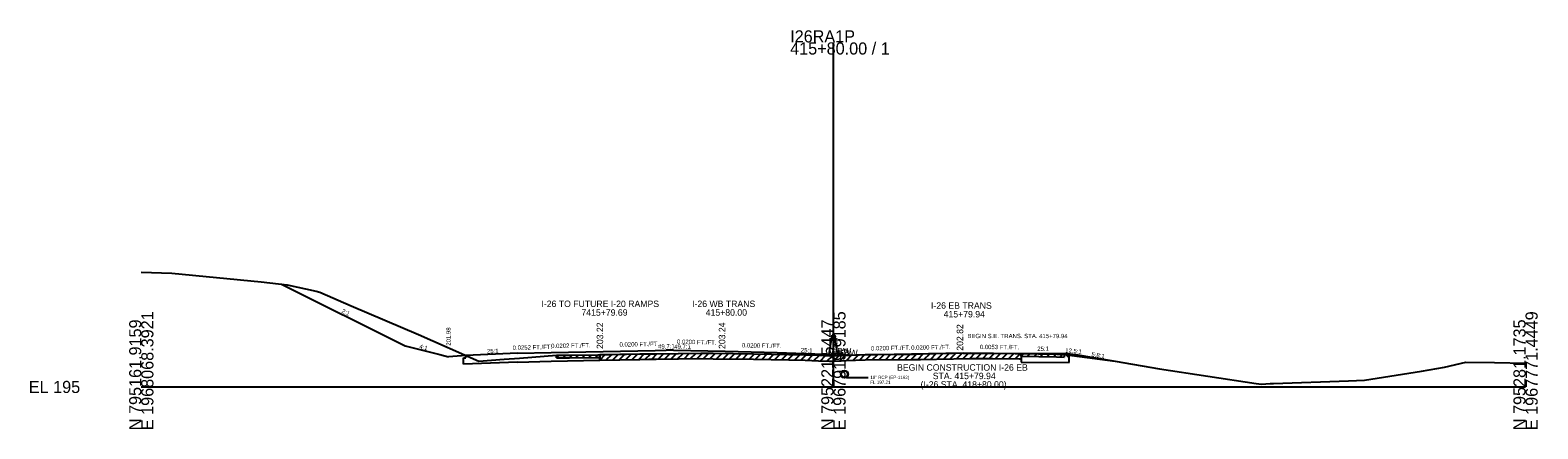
# Model space of a CAD drawing. Extents: x -44 to 4323, y -10 to 9601.
# Drawn here: x -25.7 to 322.8, y 9490.3 to 9582.5 of the extents above; entities that cross this region are included whole.
import ezdxf

# ---------------------------------------------------------------- set-up
doc = ezdxf.new("R2010")
doc.units = 0
for name, color, linetype in [('1', 7, 'Continuous'), ('DateStamp', 7, 'Continuous'), ('NotForConst', 7, 'Continuous'), ('QCQA', 7, 'Continuous'), ('RD_SHT_Bndy', 7, 'Continuous'), ('RD_SHT_Iplotshp', 7, 'Continuous'), ('RD_SHT_TX', 7, 'Continuous'), ('RD_TX_Misc1', 7, 'Continuous'), ('RD_XS_ExGround', 7, 'Continuous'), ('RD_XS_MatchLine', 7, 'Continuous'), ('RD_XS_MedBWall', 7, 'Continuous'), ('RD_XS_Misc_Line', 7, 'Continuous'), ('RD_XS_Pave', 7, 'Continuous'), ('RD_XS_PaveShd', 7, 'Continuous'), ('RD_XS_Pipe', 7, 'Continuous'), ('RD_XS_TX_Elev_PR', 7, 'Continuous'), ('RD_XS_TX_Profile', 7, 'Continuous'), ('RD_XS_TX_ShdSlope', 7, 'Continuous'), ('RD_XS_TX_Slope', 7, 'Continuous'), ('seal', 7, 'Continuous'), ('TR SN EXTRUDED PANEL SIGNS - GROUND MOUNTED', 7, 'Continuous')]:
    doc.layers.add(name, color=color, linetype=linetype)

msp = doc.modelspace()

# ---------------------------------------------------------------- linework, layer by layer
at = {"layer": 'DateStamp'}
msp.add_lwpolyline([(0, 9526.56), (7.08, 9526.33), (27.72, 9524.3), (33.69, 9523.63), (40.4, 9522.11), (41.25, 9521.9), (48.53, 9518.76), (64.07, 9512.11), (78.01, 9505.96), (83.92, 9506.41), (87.46, 9506.68), (95.99, 9507.33), (99.16, 9507.38), (105.5, 9507.46), (115.46, 9507.64), (117.36, 9507.67), (118.85, 9507.69), (129.37, 9507.82), (131.97, 9507.79), (141.49, 9507.69), (149.91, 9507.5), (153.45, 9507.42), (156.37, 9507.31), (159.09, 9507.2), (160, 9507.24), (161.79, 9507.32), (163.33, 9507.37), (167.35, 9507.49), (178.64, 9507.61), (180.16, 9507.63), (183.47, 9507.7), (191.8, 9507.86), (197.04, 9507.81), (202.99, 9507.75), (211.72, 9507.56), (213.37, 9507.52), (225.16, 9505.96), (235.35, 9504.22), (257.71, 9500.8), (258.92, 9500.66), (260.96, 9500.76), (261.72, 9500.78), (279.1, 9501.4), (282.77, 9501.55), (295.95, 9503.68), (301.23, 9504.61), (306.19, 9505.7), (312.82, 9505.62), (320, 9505.47)], dxfattribs=at)
at = {"layer": 'NotForConst'}
for p, q in [((95.99, 9506.71), (96.63, 9507.34)), ((97.49, 9506.73), (98.13, 9507.36)), ((98.99, 9506.75), (99.63, 9507.38)), ((100.49, 9506.77), (101.13, 9507.4)), ((101.99, 9506.79), (102.63, 9507.42)), ((103.49, 9506.81), (104.13, 9507.44)), ((104.99, 9506.83), (105.63, 9507.46)), ((105.99, 9506.22), (107.27, 9507.49)), ((107.49, 9506.24), (108.77, 9507.52)), ((108.99, 9506.27), (110.27, 9507.54)), ((110.49, 9506.3), (111.77, 9507.57)), ((111.99, 9506.32), (113.27, 9507.6)), ((113.49, 9506.35), (114.77, 9507.62)), ((114.99, 9506.38), (116.27, 9507.65)), ((116.49, 9506.4), (117.77, 9507.68)), ((117.99, 9506.43), (119.26, 9507.7)), ((119.49, 9506.45), (120.76, 9507.71)), ((120.99, 9506.47), (122.26, 9507.73)), ((122.49, 9506.48), (123.76, 9507.75)), ((123.99, 9506.5), (125.26, 9507.77)), ((125.49, 9506.52), (126.76, 9507.79)), ((126.99, 9506.54), (128.26, 9507.8)), ((128.49, 9506.56), (129.75, 9507.81)), ((129.99, 9506.56), (131.23, 9507.79)), ((131.49, 9506.54), (132.73, 9507.78)), ((132.99, 9506.52), (134.23, 9507.76)), ((134.49, 9506.51), (135.73, 9507.75)), ((135.99, 9506.49), (137.23, 9507.73)), ((137.49, 9506.48), (138.73, 9507.72)), ((138.99, 9506.46), (140.23, 9507.7)), ((140.49, 9506.45), (141.73, 9507.68)), ((141.99, 9506.43), (143.22, 9507.65)), ((143.49, 9506.39), (144.72, 9507.62)), ((144.99, 9506.36), (146.22, 9507.58)), ((146.49, 9506.33), (147.72, 9507.55)), ((147.99, 9506.29), (149.22, 9507.51)), ((149.49, 9506.26), (150.72, 9507.48)), ((150.99, 9506.22), (152.22, 9507.45)), ((152.49, 9506.19), (153.71, 9507.41)), ((153.99, 9506.15), (155.2, 9507.35)), ((155.49, 9506.09), (156.7, 9507.3)), ((156.99, 9506.04), (158.19, 9507.24)), ((158.49, 9505.97), (159.75, 9507.23)), ((159.99, 9505.99), (161.3, 9507.3)), ((161.49, 9506.06), (162.79, 9507.35)), ((162.99, 9506.11), (164.28, 9507.4)), ((164.49, 9506.15), (165.78, 9507.44)), ((165.99, 9506.2), (167.28, 9507.49)), ((167.49, 9506.24), (168.76, 9507.51)), ((168.99, 9506.26), (170.26, 9507.52)), ((170.5, 9506.27), (171.76, 9507.54)), ((172, 9506.29), (173.26, 9507.55)), ((173.5, 9506.31), (174.76, 9507.57)), ((175, 9506.32), (176.26, 9507.59)), ((176.5, 9506.34), (177.76, 9507.6)), ((178, 9506.36), (179.26, 9507.62)), ((179.5, 9506.37), (180.76, 9507.64)), ((181, 9506.39), (182.27, 9507.67)), ((182.5, 9506.42), (183.77, 9507.7)), ((184, 9506.46), (185.27, 9507.73)), ((185.5, 9506.49), (186.77, 9507.76)), ((187, 9506.51), (188.27, 9507.79)), ((188.5, 9506.54), (189.77, 9507.82)), ((190, 9506.57), (191.27, 9507.85)), ((191.5, 9506.6), (192.74, 9507.85)), ((193, 9506.6), (194.23, 9507.84)), ((194.5, 9506.58), (195.73, 9507.82)), ((196, 9506.57), (197.23, 9507.81)), ((197.5, 9506.56), (198.73, 9507.79)), ((199, 9506.54), (200.23, 9507.78)), ((200.5, 9506.53), (201.73, 9507.76)), ((202, 9506.51), (203.23, 9507.74)), ((203.37, 9507.12), (203.98, 9507.73)), ((204.87, 9507.08), (205.48, 9507.7)), ((206.37, 9507.05), (206.98, 9507.66)), ((207.87, 9507.02), (208.48, 9507.63)), ((209.37, 9506.99), (209.98, 9507.6)), ((210.87, 9506.95), (211.48, 9507.57)), ((212.37, 9506.92), (212.98, 9507.53))]:
    msp.add_line(p, q, dxfattribs=at)
at = {"layer": 'QCQA'}
for p, q in [((105.99, 9507.47), (115.28, 9507.63)), ((105.99, 9507.47), (105.99, 9506.16)), ((115.28, 9507.63), (117.36, 9507.67)), ((117.36, 9507.67), (118.99, 9507.69)), ((118.99, 9507.69), (129.37, 9507.82)), ((129.37, 9507.82), (132.18, 9507.78)), ((132.18, 9507.78), (141.49, 9507.69)), ((141.49, 9507.69), (149.72, 9507.5)), ((149.72, 9507.5), (153.45, 9507.42)), ((153.45, 9507.42), (156.52, 9507.31)), ((156.52, 9507.31), (159.09, 9507.2)), ((159.09, 9507.2), (160, 9507.24)), ((203.37, 9507.74), (203.37, 9505.7))]:
    msp.add_line(p, q, dxfattribs=at)
msp.add_lwpolyline([(202, 9507.76), (202.99, 9507.75), (203.37, 9507.74)], dxfattribs=at)
at = {"layer": 'RD_SHT_Bndy'}
for p, q in [((160, 9500), (160, 9579.67)), ((0, 9500), (160, 9500)), ((160, 9500), (320, 9500))]:
    msp.add_line(p, q, dxfattribs=at)
at = {"layer": 'RD_SHT_Iplotshp'}
for p, q in [((95.99, 9506.71), (95.99, 9507.33)), ((95.99, 9506.71), (98.97, 9506.75)), ((98.97, 9506.75), (105.5, 9506.83)), ((105.5, 9506.83), (105.99, 9506.84)), ((105.99, 9506.22), (105.99, 9507.47)), ((105.99, 9507.47), (105.99, 9506.84)), ((105.99, 9506.22), (115.28, 9506.38)), ((115.28, 9506.38), (117.36, 9506.42)), ((117.36, 9506.42), (118.99, 9506.44)), ((118.99, 9506.44), (129.37, 9506.57)), ((129.37, 9506.57), (132.18, 9506.53)), ((132.18, 9506.53), (141.49, 9506.44)), ((141.49, 9506.44), (149.72, 9506.25)), ((149.72, 9506.25), (153.45, 9506.17)), ((153.45, 9506.17), (156.52, 9506.06)), ((156.52, 9506.06), (159.09, 9505.95)), ((159.09, 9505.95), (160, 9505.99)), ((160, 9505.99), (161.79, 9506.07)), ((161.79, 9506.07), (162.96, 9506.11)), ((162.96, 9506.11), (167.35, 9506.24)), ((167.35, 9506.24), (178.49, 9506.36)), ((178.49, 9506.36), (180.16, 9506.38)), ((180.16, 9506.38), (183.79, 9506.45)), ((183.79, 9506.45), (191.8, 9506.61)), ((191.8, 9506.61), (196.84, 9506.56)), ((196.84, 9506.56), (202.99, 9506.5)), ((202.99, 9506.5), (203.37, 9506.49)), ((203.37, 9507.74), (203.37, 9506.49)), ((203.37, 9507.12), (203.37, 9507.74)), ((203.37, 9507.12), (211.53, 9506.94)), ((211.53, 9506.94), (213.37, 9506.9)), ((213.37, 9507.52), (213.37, 9506.9))]:
    msp.add_line(p, q, dxfattribs=at)
at = {"layer": 'RD_TX_Misc1'}
for p in [(69, 9507.48), (73, 9507.14)]:
    msp.add_line(p, (71, 9506.98), dxfattribs=at)
at = {"layer": 'RD_XS_Misc_Line'}
for p, q in [((74.5, 9506.72), (75, 9506.74)), ((74.5, 9505.24), (74.5, 9506.72)), ((87, 9505.74), (74.5, 9505.24)), ((75, 9506.74), (75, 9507.3)), ((87, 9505.74), (94.77, 9505.94)), ((94.77, 9505.94), (105.99, 9506.16)), ((203.37, 9505.7), (214.5, 9505.64)), ((214, 9507.12), (214, 9507.7)), ((214, 9507.12), (214.5, 9507.12)), ((214.5, 9505.64), (214.5, 9507.12))]:
    msp.add_line(p, q, dxfattribs=at)
at = {"layer": 'RD_XS_Pave'}
for p, q in [((32.42, 9523.77), (61, 9509.48)), ((61, 9509.48), (69, 9507.48)), ((216, 9507.54), (225.16, 9505.96))]:
    msp.add_line(p, q, dxfattribs=at)
at = {"layer": 'RD_XS_PaveShd'}
for p, q in [((75, 9507.3), (73, 9507.14)), ((214, 9507.7), (216, 9507.54))]:
    msp.add_line(p, q, dxfattribs=at)
at = {"layer": 'RD_XS_Pipe'}
msp.add_line((163.04, 9502.21), (168.04, 9502.21), dxfattribs=at)
for radius in [0.85, 0.75]:
    msp.add_circle((162.54, 9502.96), radius, dxfattribs=at)
at = {"layer": 'RD_XS_TX_Elev_PR'}
for p, q in [((118.78, 9508.46), (121.33, 9508.51)), ((123, 9508.48), (121.33, 9508.51)), ((147, 9508), (160, 9507.48)), ((87, 9507.78), (75, 9507.3)), ((160, 9507.48), (160, 9507.1)), ((160, 9507.46), (160, 9507.24)), ((166, 9507.34), (160, 9507.1)), ((202, 9507.76), (214, 9507.7))]:
    msp.add_line(p, q, dxfattribs=at)
at = {"layer": 'RD_XS_TX_ShdSlope'}
for p, q in [((159, 9507.5), (159.67, 9511.98)), ((160.33, 9511.98), (159.67, 9511.98)), ((161.05, 9507.14), (160.33, 9511.98))]:
    msp.add_line(p, q, dxfattribs=at)
at = {"layer": 'RD_XS_TX_Slope'}
for p, q in [((87, 9507.78), (94.77, 9507.98)), ((94.77, 9507.98), (106.77, 9508.22)), ((106.77, 9508.22), (118.78, 9508.46)), ((123, 9508.48), (135, 9508.24)), ((135, 9508.24), (147, 9508)), ((190, 9507.82), (166, 9507.34)), ((190, 9507.82), (202, 9507.76))]:
    msp.add_line(p, q, dxfattribs=at)

# ---------------------------------------------------------------- texts
at = {"layer": '1'}
for s, p in [('I-26 TO FUTURE I-20 RAMPS', (92.5, 9518.47)), ('I-26 WB TRANS', (127.33, 9518.47)), ('I-26 EB TRANS', (182.56, 9518.07)), ('7415+79.69', (101.75, 9516.47)), ('415+80.00', (130.48, 9516.47)), ('415+79.94', (185.48, 9516.07))]:
    msp.add_text(s, height=1.5, dxfattribs=at).set_placement(p)
at = {"layer": 'RD_SHT_Bndy'}
for s, p in [('I26RA1P', (150, 9579.67)), ('415+80.00 / 1', (150, 9576.87)), ('EL 195', (-26, 9498.6))]:
    msp.add_text(s, height=2.8, dxfattribs=at).set_placement(p)
for s, p in [('N 795161.9159', (0, 9490)), ('E 1968068.3921', (2.8, 9490)), ('N 795221.5447', (160, 9490)), ('E 1967919.9185', (162.8, 9490)), ('N 795281.1735', (320, 9490)), ('E 1967771.4449', (322.8, 9490))]:
    msp.add_text(s, height=2.8, rotation=90, dxfattribs=at).set_placement(p)
at = {"layer": 'RD_SHT_TX'}
msp.add_text('202.24', height=1, rotation=90, dxfattribs=at).set_placement((161, 9507.24))
at = {"layer": 'RD_XS_ExGround'}
for s, rotation, p in [('25:1', 2.29, (79.93, 9507.75)), ('49.7:1', 1.1535, (119.48, 9508.85)), ('49.7:1', 1.1535, (123.2, 9508.8)), ('25:1', 357.7094, (152.46, 9508.02)), ('25:1', 2.2903, (160.93, 9507.39)), ('25:1', 0.6258, (207.13, 9508.33))]:
    msp.add_text(s, height=1, rotation=rotation, dxfattribs=at).set_placement(p)
at = {"layer": 'RD_XS_MatchLine'}
for s, height, p in [('BEGIN S.E. TRANS. STA. 415+79.94', 1, (190.98, 9511.28)), ('BEGIN CONSTRUCTION I-26 EB', 1.5, (174.72, 9503.76)), ('(I-26 STA. 418+80.00)', 1.5, (180.13, 9499.83)), ('STA. 415+79.94', 1.5, (182.96, 9501.8))]:
    msp.add_text(s, height=height, dxfattribs=at).set_placement(p)
at = {"layer": 'RD_XS_MedBWall'}
msp.add_text('12.5:1', height=1, rotation=355.4267, dxfattribs=at).set_placement((213.55, 9507.98))
at = {"layer": 'RD_XS_Pipe'}
for s, p in [('18" RCP (EP-1162)', (168.53, 9501.84)), ('FL 197.21', (168.53, 9500.71))]:
    msp.add_text(s, height=0.75, dxfattribs=at).set_placement(p)
at = {"layer": 'RD_XS_TX_Profile'}
for s, p in [('WBW', (159, 9507.48)), ('EBW', (161.05, 9507.14))]:
    msp.add_text(s, height=1.5, dxfattribs=at).set_placement(p)
at = {"layer": 'seal'}
for s, p in [(' 203.22', (106.77, 9508.22)), (' 203.24', (135, 9508.22)), (' 202.82', (190, 9507.82))]:
    msp.add_text(s, height=1.5, rotation=90, dxfattribs=at).set_placement(p)
at = {"layer": 'TR SN EXTRUDED PANEL SIGNS - GROUND MOUNTED'}
for s, rotation, p in [('2:1', 333.4349, (46.2, 9517.24)), ('201.98', 90, (71.5, 9509.54)), ('4:1', 345.9638, (64.2, 9508.92)), ('0.0252 FT./FT.', 1.4427, (85.86, 9508.56)), ('0.0202 FT./FT.', 1.1562, (94.75, 9508.98)), ('0.0200 FT./FT.', 1.1535, (110.56, 9509.3)), ('0.0200 FT./FT.', 358.8542, (123.84, 9509.98)), ('0.0200 FT./FT.', 358.8542, (138.83, 9509.15)), ('0.0200 FT./FT.', 1.1503, (168.7, 9508.42)), ('0.0200 FT./FT.', 1.1503, (177.98, 9508.58)), ('0.0053 FT./FT.', 359.7951, (193.83, 9508.75)), ('5:8:1', 350.5377, (219.59, 9507.1))]:
    msp.add_text(s, height=1, rotation=rotation, dxfattribs=at).set_placement(p)

doc.saveas('drawing.dxf')
